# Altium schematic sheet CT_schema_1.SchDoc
size 289 x 339 mm
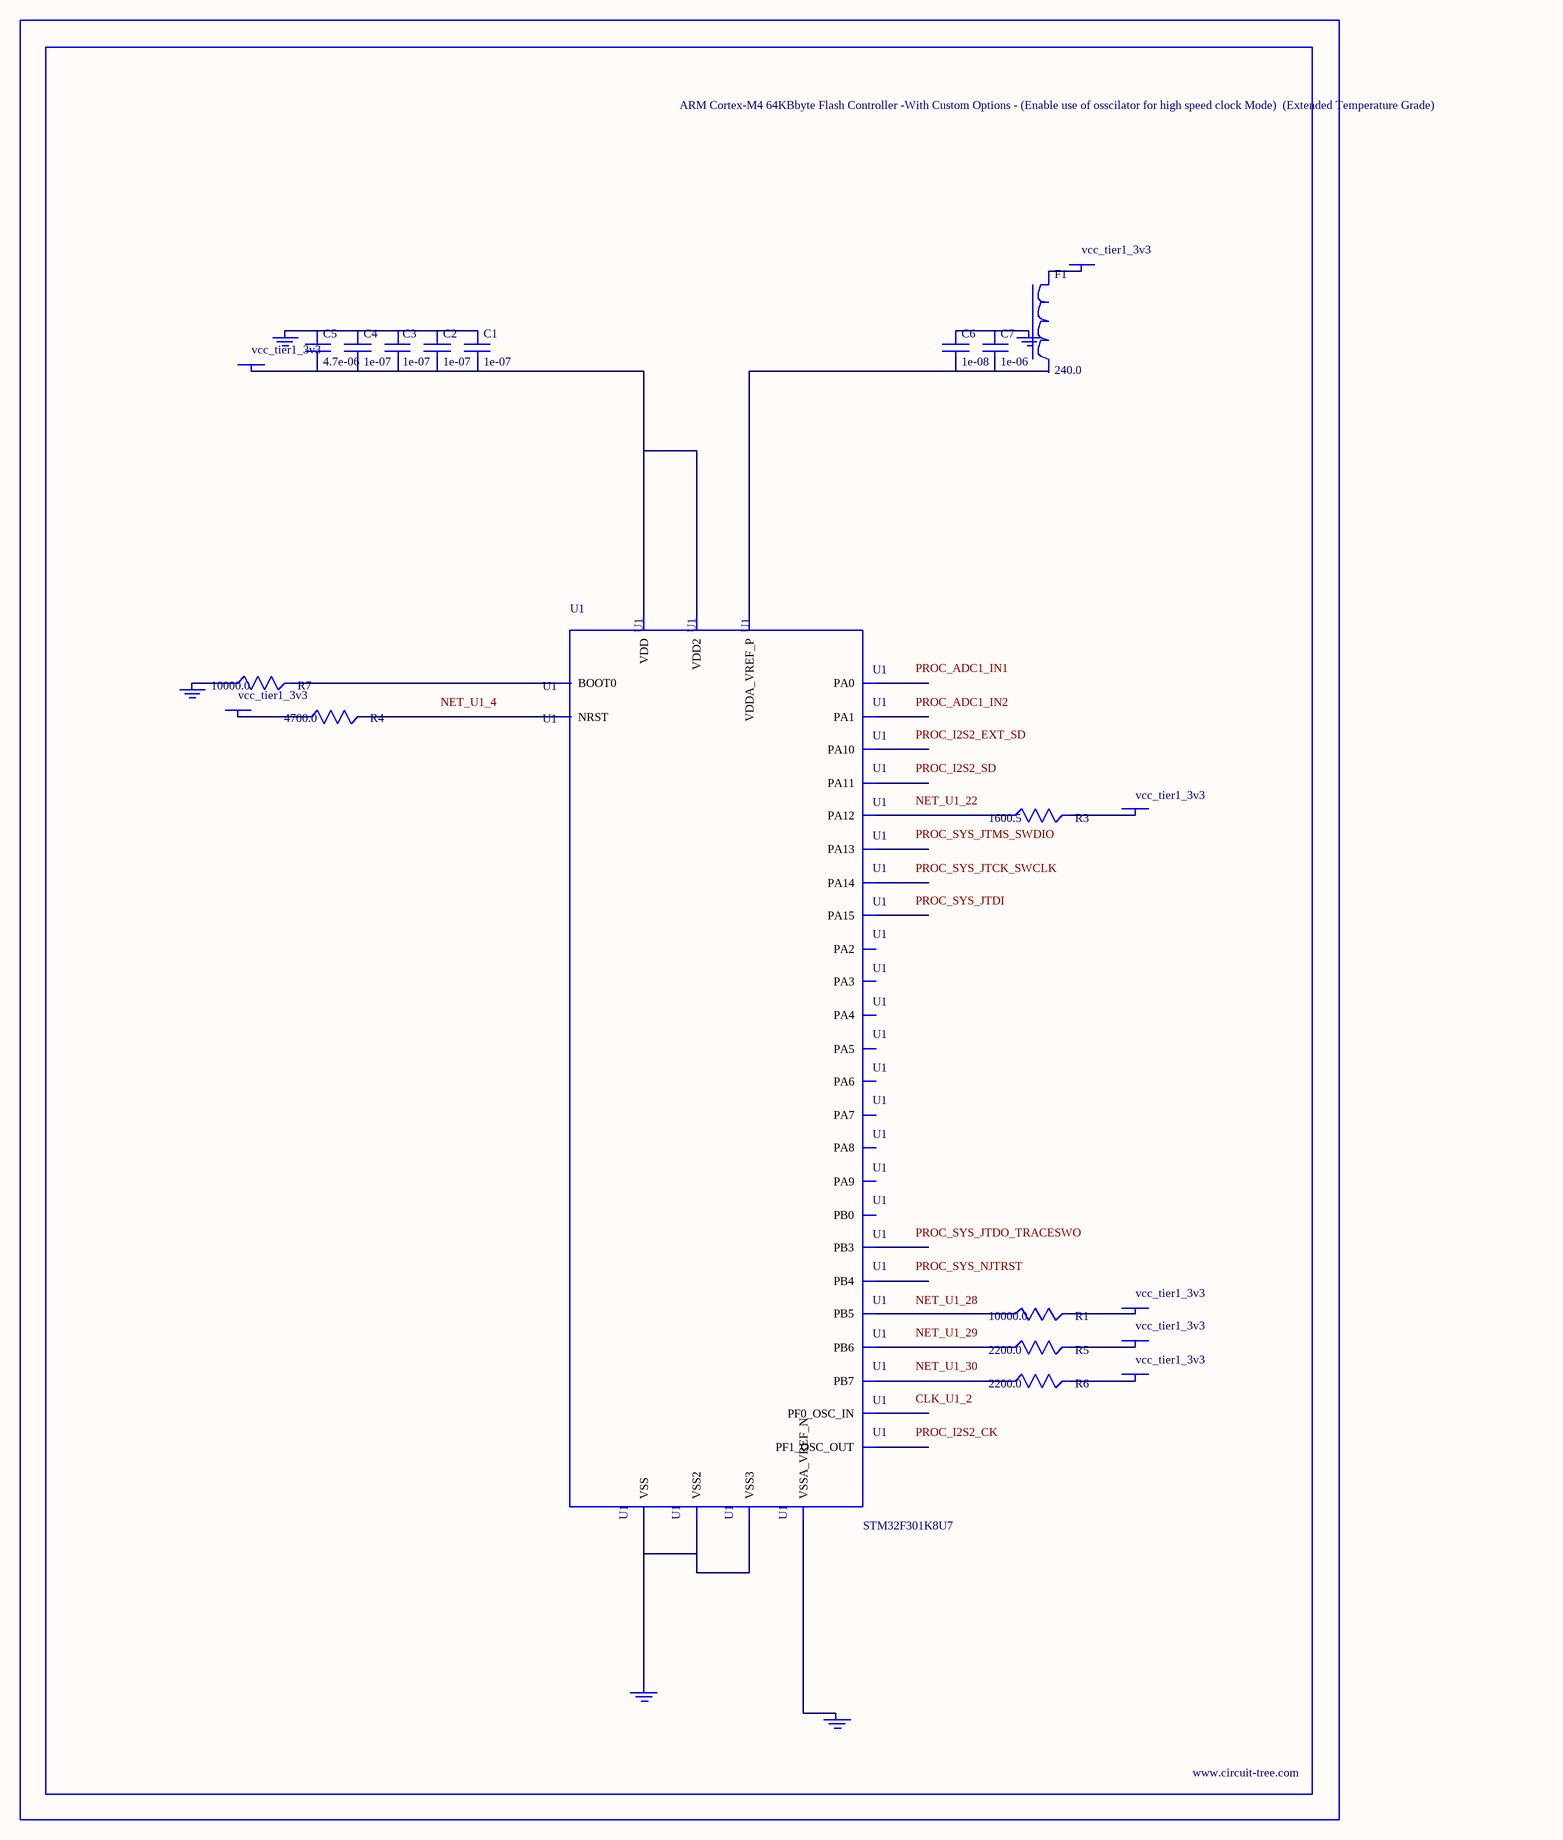
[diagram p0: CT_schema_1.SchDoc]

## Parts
BORDER0  (no value)
C1  1e-07  [C0603]
C2  1e-07  [C0603]
C3  1e-07  [C0603]
C4  1e-07  [C0603]
C5  4.7e-06  [C0603]
C6  1e-08  [C0603]
C7  1e-06  [C0603]
F1  240.0  [L0603]
GND_INSTANCE_0_0  (no value)
GND_INSTANCE_0_1  (no value)
GND_INSTANCE_0_2  (no value)
GND_INSTANCE_0_3  (no value)
GND_INSTANCE_0_4  (no value)
POWER_INSTANCE_0_0  vcc_tier1_3v3
POWER_INSTANCE_0_1  vcc_tier1_3v3
POWER_INSTANCE_0_2  vcc_tier1_3v3
POWER_INSTANCE_0_3  vcc_tier1_3v3
POWER_INSTANCE_0_4  vcc_tier1_3v3
POWER_INSTANCE_0_5  vcc_tier1_3v3
POWER_INSTANCE_0_6  vcc_tier1_3v3
R1  10000.0  [R0603]
R3  1600.5  [R0603]
R4  4700.0  [R0603]
R5  2200.0  [R0603]
R6  2200.0  [R0603]
R7  10000.0  [R0603]
U1  STM32F301K8U7  [UFQFPN32]

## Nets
NetC1_1: C1.1 C2.1 C3.1 C4.1 C5.1 GND_INSTANCE_0_0.0(GND)
NetC1_2: C1.2 C2.2 C3.2 C4.2 C5.2 POWER_INSTANCE_0_0.0(PWR) U1.1(VDD) U1.17(VDD2)
NetC6_1: C6.1 C7.1 GND_INSTANCE_0_1.0(GND)
NetC6_2: C6.2 C7.2 U1.5(VDDA_VREF_P)
NetF1_1: F1.1 POWER_INSTANCE_0_1.0(PWR)
NetGND_INSTANCE_0_2_0: GND_INSTANCE_0_2.0(GND) U1.6(VSSA_VREF_N)
NetGND_INSTANCE_0_3_0: GND_INSTANCE_0_3.0(GND) R7.1
NetGND_INSTANCE_0_4_0: GND_INSTANCE_0_4.0(GND) U1.16(VSS) U1.32(VSS2) U1.EPAD(VSS3)
NetPOWER_INSTANCE_0_2_0: POWER_INSTANCE_0_2.0(PWR) R4.1
NetPOWER_INSTANCE_0_3_0: POWER_INSTANCE_0_3.0(PWR) R3.2
NetPOWER_INSTANCE_0_4_0: POWER_INSTANCE_0_4.0(PWR) R1.2
NetPOWER_INSTANCE_0_5_0: POWER_INSTANCE_0_5.0(PWR) R5.2
NetPOWER_INSTANCE_0_6_0: POWER_INSTANCE_0_6.0(PWR) R6.2
NetR1_1: R1.1 U1.28(PB5)
NetR3_1: R3.1 U1.22(PA12)
NetR4_2: R4.2 U1.4(NRST)
NetR5_1: R5.1 U1.29(PB6)
NetR6_1: R6.1 U1.30(PB7)
NetR7_2: R7.2 U1.31(BOOT0)

Not connected (* = marked no-connect by the designer): F1 2; U1 2(PF0_OSC_IN) 3(PF1_OSC_OUT) 7(PA0) 8(PA1) 9(PA2) 10(PA3) 11(PA4) 12(PA5) 13(PA6) 14(PA7) 15(PB0) 18(PA8) 19(PA9) 20(PA10) 21(PA11) 23(PA13) 24(PA14) 25(PA15) 26(PB3) 27(PB4)

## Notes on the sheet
- Labels drawn without touching a wire or pin: CLK_U1_2, NET_U1_4, NET_U1_22, NET_U1_28, NET_U1_29, NET_U1_30, PROC_ADC1_IN1, PROC_ADC1_IN2, PROC_I2S2_CK, PROC_I2S2_EXT_SD, PROC_I2S2_SD, PROC_SYS_JTCK_SWCLK, PROC_SYS_JTDI, PROC_SYS_JTDO_TRACESWO, PROC_SYS_JTMS_SWDIO, PROC_SYS_NJTRST

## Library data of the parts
BORDER0 = BORDER_PAGE0
C1-C4 = 06035C104K4Z2A
C5 = GRM188R6YA475KE15D
C6 = 06035C103K4Z2A
C7 = C0603C105K3RACTU
F1 = Z0603C241ASMST
GND_INSTANCE_0_0-GND_INSTANCE_0_4 = GND
POWER_INSTANCE_0_0-POWER_INSTANCE_0_6 = PWR
R1 R7 = RC0603JR-0710KL
R3 = R3
R4 = RC0603JR-074K7L
R5 R6 = RC0603JR-072K2L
